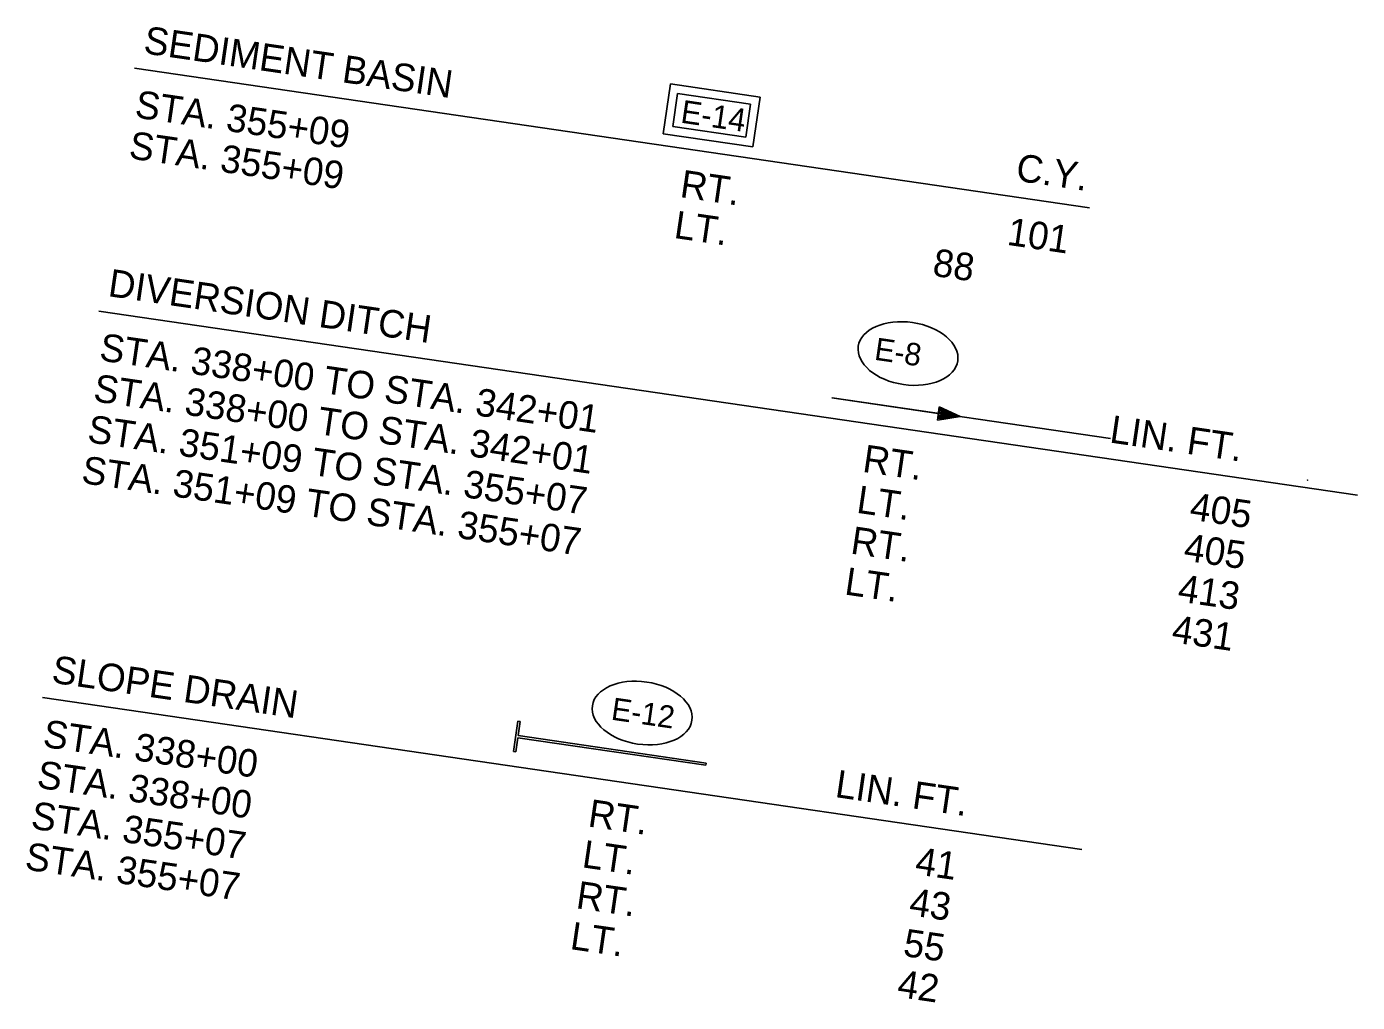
# Model space of a CAD drawing. Extents: x 882623 to 886086, y 1564278 to 1565583.
# Drawn here: x 882623.3 to 882925.3, y 1565361.7 to 1565583.2 of the extents above; entities that cross this region are included whole.
import ezdxf

# ---------------------------------------------------------------- set-up
doc = ezdxf.new("R2010")
doc.units = 0
doc.layers.add('R_Erosion_STG 2', color=7, linetype='Continuous')
doc.layers.add('S_RDW_PT_SYM', color=7, linetype='Continuous')

msp = doc.modelspace()

# ---------------------------------------------------------------- linework, layer by layer
at = {"layer": 'R_Erosion_STG 2'}
for p, q in [((882647.79, 1565573.69), (882864.51, 1565542.03)), ((882769.42, 1565570.14), (882767.77, 1565558.85)), ((882769.42, 1565570.14), (882789.78, 1565567.16)), ((882771.05, 1565567.95), (882769.95, 1565560.48)), ((882771.05, 1565567.95), (882787.59, 1565565.53)), ((882787.59, 1565565.53), (882786.5, 1565558.06)), ((882789.78, 1565567.16), (882788.12, 1565555.87)), ((882769.95, 1565560.48), (882786.5, 1565558.06)), ((882767.77, 1565558.85), (882788.12, 1565555.87)), ((882639.74, 1565518.57), (882925.27, 1565476.85)), ((882806.08, 1565498.9), (882869.29, 1565489.65)), ((882830.4, 1565496.86), (882829.97, 1565493.87)), ((882833.85, 1565495.02), (882830.29, 1565496.1)), ((882833.89, 1565495.12), (882830.35, 1565496.47)), ((882835.13, 1565494.65), (882830.4, 1565496.86)), ((882829.97, 1565493.87), (882835.13, 1565494.65)), ((882830.02, 1565494.25), (882833.8, 1565494.53)), ((882830.08, 1565494.63), (882833.8, 1565494.64)), ((882830.13, 1565494.99), (882833.8, 1565494.74)), ((882833.83, 1565494.93), (882830.24, 1565495.73)), ((882626.93, 1565430.88), (882862.79, 1565396.42)), ((882733.8, 1565418.64), (882734.81, 1565425.57)), ((882734.81, 1565425.57), (882735.32, 1565425.49)), ((882734.86, 1565422.28), (882735.32, 1565425.49)), ((882734.31, 1565418.56), (882734.78, 1565421.77)), ((882777.46, 1565415.53), (882734.78, 1565421.77)), ((882777.53, 1565416.05), (882734.86, 1565422.28)), ((882733.8, 1565418.64), (882734.31, 1565418.56)), ((882777.53, 1565416.05), (882777.46, 1565415.53))]:
    msp.add_line(p, q, dxfattribs=at)
msp.add_lwpolyline([(882806.07, 1565498.9), (882834.8, 1565494.69)], dxfattribs=at)
for centre in [(882823.32, 1565508.96), (882763, 1565427.39)]:
    msp.add_ellipse(centre, major_axis=(11.29, -1.65), ratio=0.622952, dxfattribs=at)
at = {"layer": 'S_RDW_PT_SYM'}
msp.add_lwpolyline([(882913.98, 1565480.24), (882913.98, 1565480.27), (882913.98, 1565480.24), (882913.96, 1565480.24), (882913.98, 1565480.24), (882913.99, 1565480.22), (882913.98, 1565480.24), (882914.01, 1565480.25)], dxfattribs=at)

# ---------------------------------------------------------------- texts
at = {"layer": 'R_Erosion_STG 2'}
for s, height, rotation, p in [('SEDIMENT BASIN', 6.25, 351.6881, (882649.67, 1565577.13)), ('STA. 355+09', 6.25, 351.6881, (882647.68, 1565562.57)), ('E-14', 5.209, 351.6765, (882771.54, 1565561.38)), ('STA. 355+09', 6.25, 351.6881, (882646.33, 1565553.29)), ('C.Y.', 6.25, 351.6881, (882847.57, 1565548.22)), ('RT.', 6.25, 351.6881, (882771.37, 1565544.5)), ('LT.', 6.25, 351.6881, (882770.01, 1565535.22)), ('101', 6.25, 351.6881, (882845.58, 1565533.66)), ('    88', 6.25, 351.6881, (882819.49, 1565528)), ('DIVERSION DITCH', 6.25, 351.6881, (882641.62, 1565522.01)), ('STA. 338+00 TO STA. 342+01', 6.25, 351.6881, (882639.63, 1565507.45)), ('E-8 ', 5.079, 351.6822, (882815.49, 1565507.58)), ('STA. 338+00 TO STA. 342+01', 6.25, 351.6881, (882638.27, 1565498.17)), ('STA. 351+09 TO STA. 355+07', 6.25, 351.6881, (882636.92, 1565488.89)), ('  LIN. FT.', 6.25, 351.6881, (882864.26, 1565489.48)), ('RT.', 6.25, 351.6881, (882812.79, 1565482.15)), ('STA. 351+09 TO STA. 355+07', 6.25, 351.6881, (882635.56, 1565479.62)), ('LT.', 6.25, 351.6881, (882811.43, 1565472.87)), ('405', 6.25, 351.6881, (882887, 1565471.31)), ('RT.', 6.25, 351.6881, (882810.08, 1565463.6)), ('405', 6.25, 351.6881, (882885.65, 1565462.03)), ('LT.', 6.25, 351.6881, (882808.72, 1565454.32)), ('413', 6.25, 351.6881, (882884.29, 1565452.75)), ('431', 6.25, 351.6881, (882882.94, 1565443.48)), ('SLOPE DRAIN', 6.25, 351.6881, (882628.81, 1565434.32)), ('E-12', 5.079, 351.6822, (882755.77, 1565425.91)), ('STA. 338+00', 6.25, 351.6881, (882626.82, 1565419.75)), ('STA. 338+00', 6.25, 351.6881, (882625.46, 1565410.48)), ('  LIN. FT.', 6.25, 351.6881, (882801.97, 1565409.02)), ('STA. 355+07', 6.25, 351.6881, (882624.11, 1565401.2)), ('RT.', 6.25, 351.6881, (882750.5, 1565401.68)), ('STA. 355+07', 6.25, 351.6881, (882622.75, 1565391.92)), ('LT.', 6.25, 351.6881, (882749.15, 1565392.41)), ('41', 6.25, 351.6881, (882824.72, 1565390.84)), ('RT.', 6.25, 351.6881, (882747.79, 1565383.13)), ('43', 6.25, 351.6881, (882823.36, 1565381.56)), ('LT.', 6.25, 351.6881, (882746.44, 1565373.85)), ('55', 6.25, 351.6881, (882822.01, 1565372.29)), ('42', 6.25, 351.6881, (882820.65, 1565363.01))]:
    msp.add_text(s, height=height, rotation=rotation, dxfattribs=at).set_placement(p)

doc.saveas('drawing.dxf')
